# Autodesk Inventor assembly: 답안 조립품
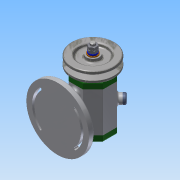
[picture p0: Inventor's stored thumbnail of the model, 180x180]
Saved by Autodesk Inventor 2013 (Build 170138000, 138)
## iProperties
Created: 2017-06
Part Number: 답안 조립품
Document SubType Name: Weldment
Designer: Administrator
Weld Material: Welded Aluminum-6061
Author: Administrator
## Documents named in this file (14)
- C:\Users\Administrator\Desktop\470608V1019\답안 조립품.iam
- C:\Users\Administrator\Desktop\470608V1019\본체.ipt
- C:\Users\Administrator\Desktop\470608V1019\V벨트풀리.ipt
- C:\Users\Administrator\Desktop\470608V1019\뒤커버.ipt
- C:\Users\Administrator\Desktop\470608V1019\베어링 15 x 32 x 9.ipt
- C:\Users\Administrator\Desktop\470608V1019\앞커버.ipt
- C:\Users\Administrator\Desktop\470608V1019\오일 실 15 25 7.ipt
- C:\Users\Administrator\Desktop\470608V1019\축.ipt
- C:\Users\Administrator\Desktop\470608V1019\키 3 x 3 x 12.ipt
- C:\Users\Administrator\Desktop\470608V1019\너트 M 8.ipt
- C:\Users\Administrator\Desktop\470608V1019\스프링와셔 8.ipt
- C:\Users\Administrator\Desktop\470608V1019\와셔 8x17.ipt
- C:\Users\Administrator\Desktop\470608V1019\고무캡.ipt
- C:\Users\Administrator\Desktop\470608V1019\볼트 M4 x 12.ipt
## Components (2 placed, 2 different names)
1. V벨트풀리:1
2. 고무캡:1
